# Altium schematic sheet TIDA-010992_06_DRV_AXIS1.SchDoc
size 431 x 279 mm; Date: Not shown in title block; ApprovedBy: Not shown in title block; CheckedBy: Not shown in title block; Author: Not shown in title block; CompanyName: Not shown in title block; Engineer: Not shown in title block; Organization: Not shown in title block; Address1: Not shown in title block; Address2: Not shown in title block; Address3: Not shown in title block; Address4: Not shown in title block; DocumentNumber: 6; Revision: Use project parameter SCH_Rev; SheetNumber: 6; SheetTotal: 13; PageSetup: Record=PageOptions¦CenterHorizontal=True¦CenterVertical=True¦PrintScale=1.00¦XCorrection=1.00¦YCorrection=1.00¦PrintKind=0¦BorderSize=5000000¦LeftOffset=0¦BottomOffset=0¦Orientation=2¦PaperLength=1000¦PaperWidth=1000¦Scale=100¦PaperSource=15¦PrintQuality=600¦MediaType=1¦DitherType=10¦PaperKind=Letter¦PrintScaleMode=1
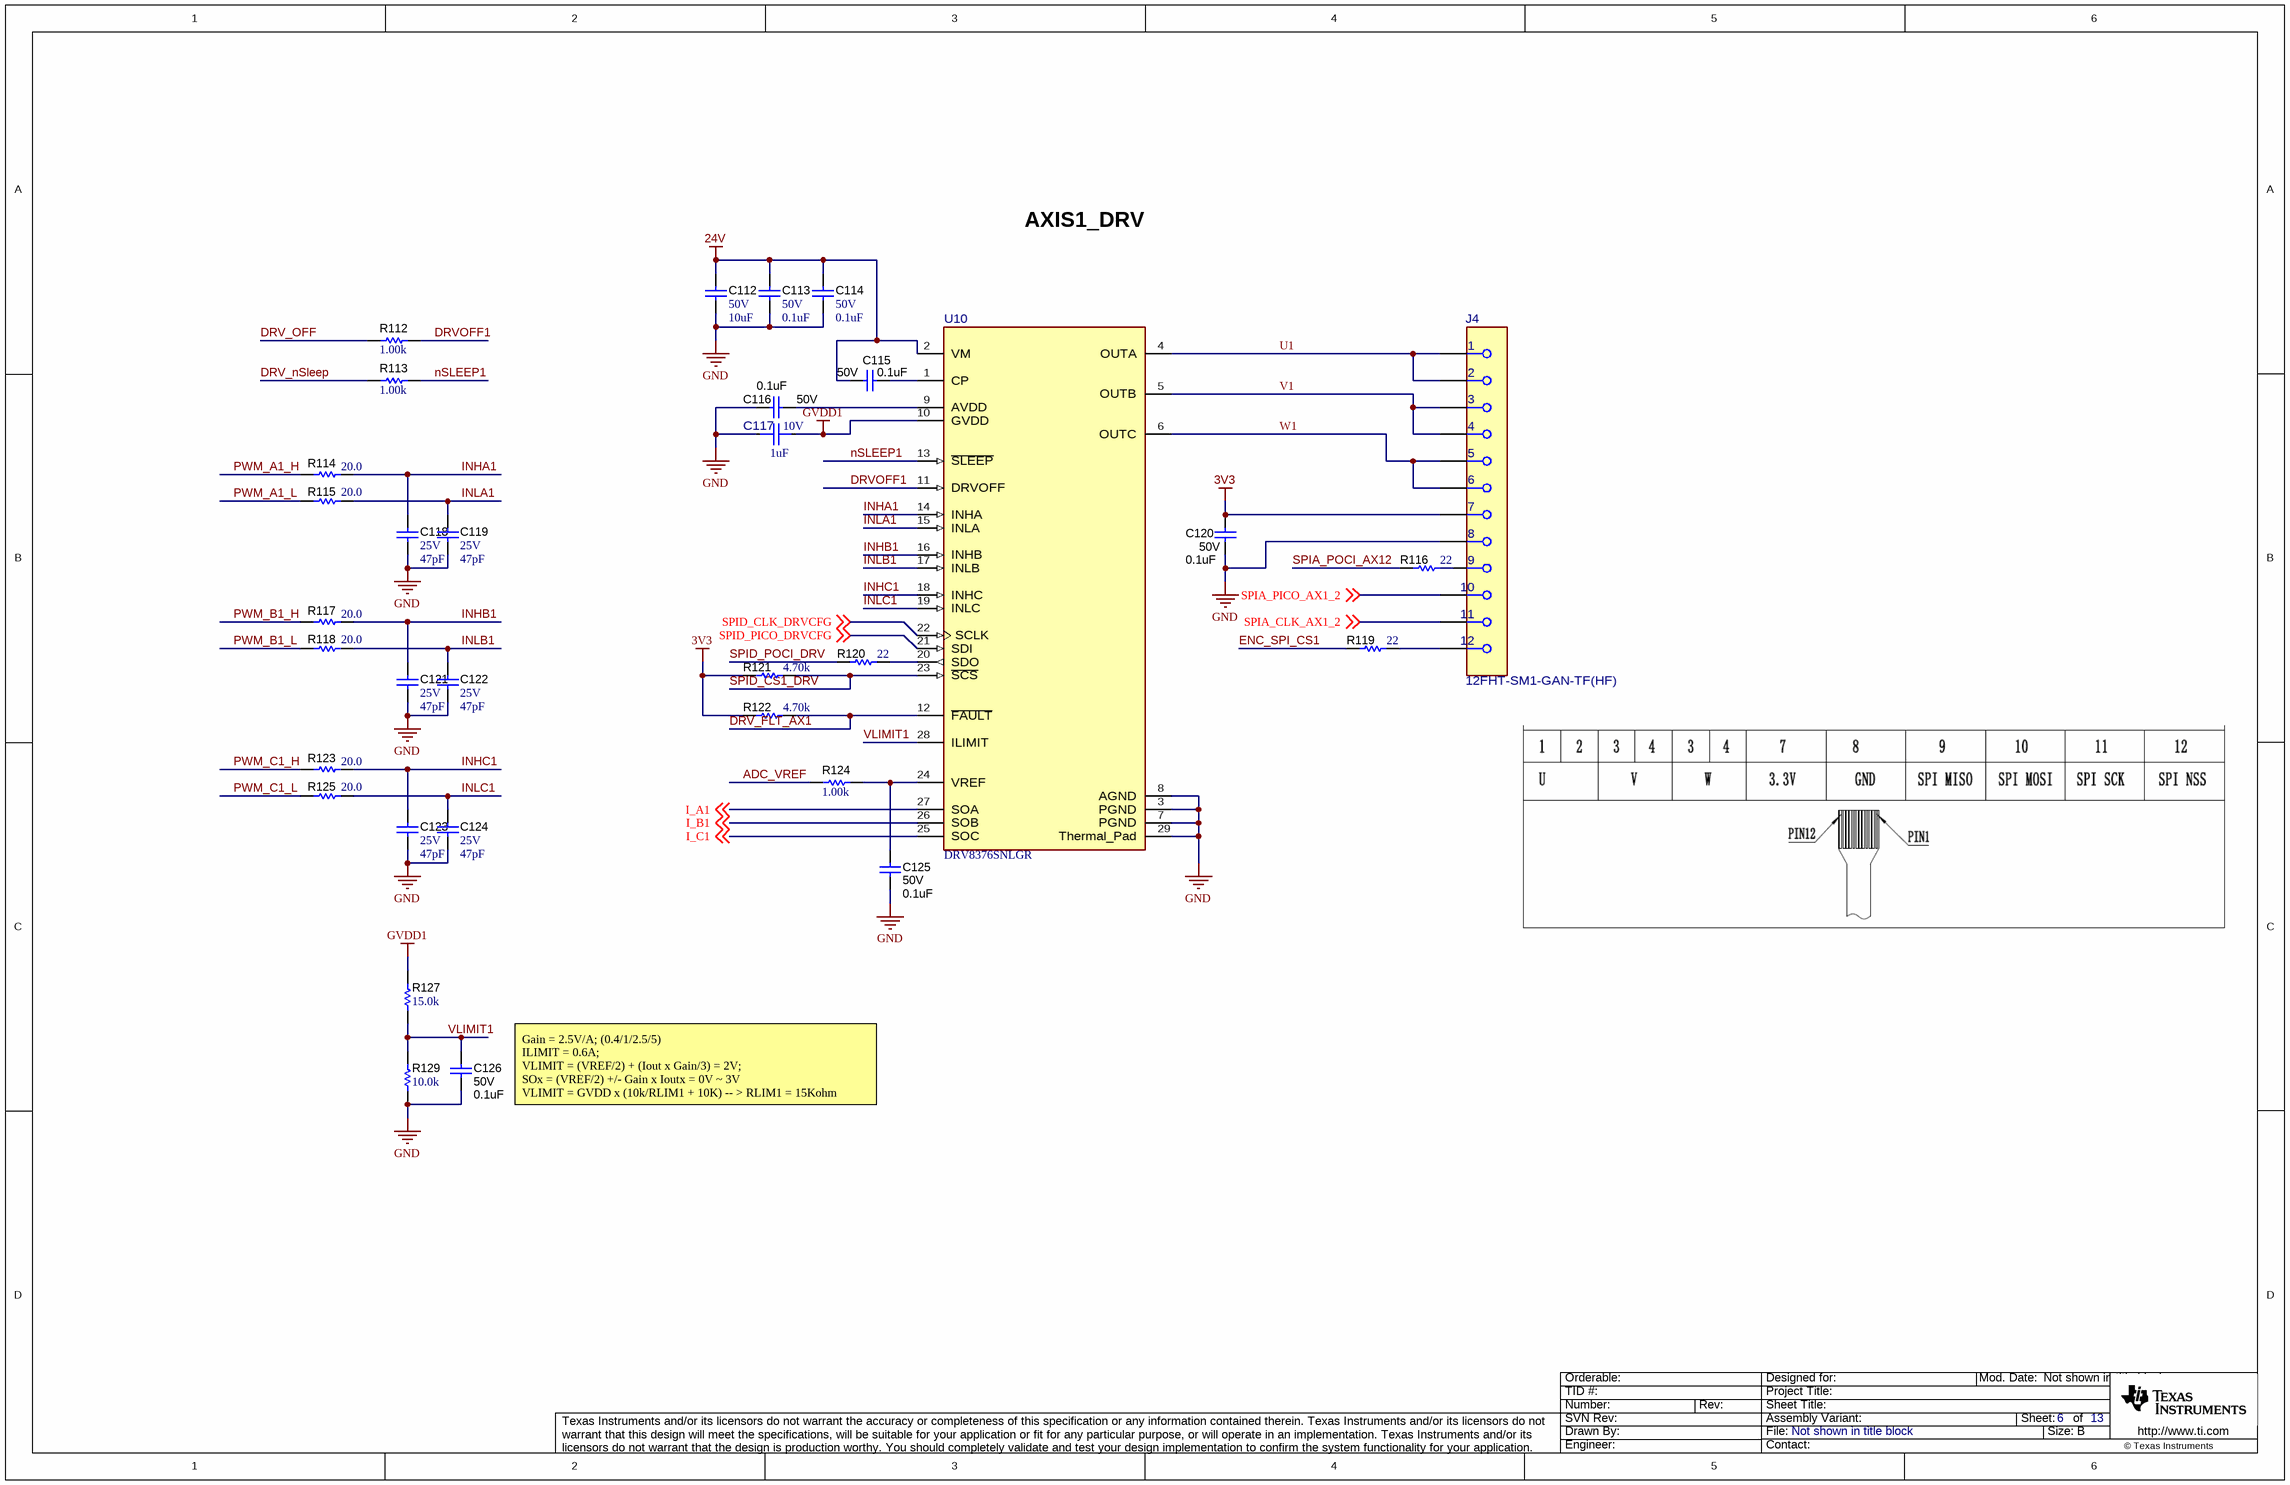
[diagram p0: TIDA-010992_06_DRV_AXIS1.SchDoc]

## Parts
C112  VDC_V: 50V  ValueDisplayed: 10uF  [1206_180]  (hidden comment: CL31B106KBHNNNE)
C113  VDC_V: 50V  ValueDisplayed: 0.1uF  [0402]  (hidden comment: C1005X7R1H104K050BE)
C114  VDC_V: 50V  ValueDisplayed: 0.1uF  [0402]  (hidden comment: C1005X7R1H104K050BE)
C115  VDC_V: 50V  ValueDisplayed: 0.1uF  [0402]  (hidden comment: CGA2B3X7R1H104M050BB)
C116  VDC_V: 50V  ValueDisplayed: 0.1uF  [0402]  (hidden comment: CGA2B3X7R1H104M050BB)
C117  VDC_V: 10V  ValueDisplayed: 1uF  [FP-GMC04X7R105K10NT_0402-MFG]  (hidden comment: GMC04X7R105K10NT)
C118  VDC_V: 25V  ValueDisplayed: 47pF  [0201_033]  (hidden comment: GRM0335C1E470JA01D)
C119  VDC_V: 25V  ValueDisplayed: 47pF  [0201_033]  (hidden comment: GRM0335C1E470JA01D)
C120  VDC_V: 50V  ValueDisplayed: 0.1uF  [0402]  (hidden comment: CGA2B3X7R1H104M050BB)
C121  VDC_V: 25V  ValueDisplayed: 47pF  [0201_033]  (hidden comment: GRM0335C1E470JA01D)
C122  VDC_V: 25V  ValueDisplayed: 47pF  [0201_033]  (hidden comment: GRM0335C1E470JA01D)
C123  VDC_V: 25V  ValueDisplayed: 47pF  [0201_033]  (hidden comment: GRM0335C1E470JA01D)
C124  VDC_V: 25V  ValueDisplayed: 47pF  [0201_033]  (hidden comment: GRM0335C1E470JA01D)
C125  VDC_V: 50V  ValueDisplayed: 0.1uF  [0402]  (hidden comment: CGA2B3X7R1H104M050BB)
C126  VDC_V: 50V  ValueDisplayed: 0.1uF  [0402]  (hidden comment: CGA2B3X7R1H104M050BB)
J4  12FHT-SM1-GAN-TF(HF)  [FP-12FHT-SM1-GAN-TF(HF)_CONN_FPC_12-MFG]
R112  ValueDisplayed: 1.00k  [0402]  (hidden comment: CRCW04021K00FKED)
R113  ValueDisplayed: 1.00k  [0402]  (hidden comment: CRCW04021K00FKED)
R114  ValueDisplayed: 20.0  [0201_033]  (hidden comment: CRCW020120R0FNED)
R115  ValueDisplayed: 20.0  [0201_033]  (hidden comment: CRCW020120R0FNED)
R116  ValueDisplayed: 22  [0201]  (hidden comment: ERJ-1GNJ220C)
R117  ValueDisplayed: 20.0  [0201_033]  (hidden comment: CRCW020120R0FNED)
R118  ValueDisplayed: 20.0  [0201_033]  (hidden comment: CRCW020120R0FNED)
R119  ValueDisplayed: 22  [0201]  (hidden comment: ERJ-1GNJ220C)
R120  ValueDisplayed: 22  [0201]  (hidden comment: ERJ-1GNJ220C)
R121  ValueDisplayed: 4.70k  [0201]  (hidden comment: RC0201FR-7D4K7L)
R122  ValueDisplayed: 4.70k  [0201]  (hidden comment: RC0201FR-7D4K7L)
R123  ValueDisplayed: 20.0  [0201_033]  (hidden comment: CRCW020120R0FNED)
R124  ValueDisplayed: 1.00k  [0402]  (hidden comment: CRCW04021K00FKED)
R125  ValueDisplayed: 20.0  [0201_033]  (hidden comment: CRCW020120R0FNED)
R127  ValueDisplayed: 15.0k  [0402]  (hidden comment: RC0402FR-0715KL)
R129  ValueDisplayed: 10.0k  [0402L]  (hidden comment: CRCW040210K0FKED)
U10  DRV8376SNLGR  [NLG0028A-MFG]

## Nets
3V3: C120.2 J4.7 R121.2 R122.2
24V: C112.1 C113.1 C114.1 C115.1 U10.2(VM)
GND: C112.2 C113.2 C114.2 C116.1 C117.1 C118.2 C119.2 C120.1 C121.2 C122.2 C123.2 C124.2 C125.1 C126.1 J4.8 R129.1 U10.3(PGND) U10.7(PGND) U10.8(AGND) U10.29(Thermal_Pad)
GVDD1: C117.2 R127.2 U10.10(GVDD)
ADC_VREF: R124.1
DRV_FLT_AX1: R122.1 U10.12(~{FAULT})
DRV_nSleep: R113.1
DRV_OFF: R112.1
DRVOFF1: R112.2 U10.11(DRVOFF)
ENC_SPI_CS1: R119.1
I_A1: U10.27(SOA) ; off-sheet I_A1
I_B1: U10.26(SOB) ; off-sheet I_B1
I_C1: U10.25(SOC) ; off-sheet I_C1
INHA1: C118.1 R114.2 U10.14(INHA)
INHB1: C121.1 R117.2 U10.16(INHB)
INHC1: C123.1 R123.2 U10.18(INHC)
INLA1: C119.1 R115.2 U10.15(INLA)
INLB1: C122.1 R118.2 U10.17(INLB)
INLC1: C124.1 R125.2 U10.19(INLC)
nSLEEP1: R113.2 U10.13(~{SLEEP})
PWM_A1_H: R114.1
PWM_A1_L: R115.1
PWM_B1_H: R117.1
PWM_B1_L: R118.1
PWM_C1_H: R123.1
PWM_C1_L: R125.1
SPIA_CLK_AX1_2: J4.11 ; off-sheet SPIA_CLK_AX1_2
SPIA_PICO_AX1_2: J4.10 ; off-sheet SPIA_PICO_AX1_2
SPIA_POCI_AX12: R116.1
SPID_CLK_DRVCFG: U10.22(SCLK) ; off-sheet SPID_CLK_DRVCFG
SPID_CS1_DRV: R121.1 U10.23(~{SCS})
SPID_PICO_DRVCFG: U10.21(SDI) ; off-sheet SPID_PICO_DRVCFG
SPID_POCI_DRV: R120.1
U1: J4.1 J4.2 U10.4(OUTA)
V1: J4.3 J4.4 U10.5(OUTB)
VLIMIT1: C126.2 R127.1 R129.2 U10.28(ILIMIT)
W1: J4.5 J4.6 U10.6(OUTC)
NetC115_2: C115.2 U10.1(CP)
NetC116_2: C116.2 U10.9(AVDD)
NetC125_2: C125.2 R124.2 U10.24(VREF)
NetJ4_9: J4.9 R116.2
NetJ4_12: J4.12 R119.2
NetR120_2: R120.2 U10.20(SDO)

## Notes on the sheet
- AXIS1_DRV
- Gain = 2.5V/A; (0.4/1/2.5/5)
  ILIMIT = 0.6A;
  VLIMIT = (VREF/2) + (Iout x Gain/3) = 2V;
  SOx = (VREF/2) +/- Gain x Ioutx = 0V ~ 3V
  VLIMIT = GVDD x (10k/RLIM1 + 10K) -- > RLIM1 = 15Kohm

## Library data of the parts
C112 = CMP-0008802-2: CAP, CERM, 10 uF, 50 V, +/- 10%, X7R, 1206; Manufacturer: Samsung; TaMin_C: -55°C; Polarized: N; SizeAreaWB_mm2: 10.92; Value1: Unknown; U/M: EA; Value: 10uF; TaMax_C: 125°C; SizeZ_mm: 1.8; SizeX_mm: 3.2; SizeY_mm: 1.6; Cap_Case: 1206; SizeArea_mm2: 5.12; Cap_F: 10µF; AEC Category: Q200
C113 C114 = CMP-0064946-2: CAP, CERM, 0.1 uF, 50 V,+/- 10%, X7R, 0402; Manufacturer: TDK; TaMin_C: -55°C; Polarized: N; SizeAreaWB_mm2: 3; Value1: Unknown; U/M: EA; Value: 0.1uF; TaMax_C: 125°C; SizeZ_mm: 0.6; SizeX_mm: 1; SizeY_mm: 0.5; Cap_F: 100nF; AEC Category: Q200
C115 C116 C120 C125 C126 = CMP-0006326-2: CAP, CERM, 0.1 uF, 50 V, +/- 20%, X7R, AEC-Q200 Grade 1, 0402; Manufacturer: TDK; TaMin_C: -55°C; Polarized: N; SizeAreaWB_mm2: 3; Value1: Unknown; U/M: EA; Value: 0.1uF; TaMax_C: 125°C; SizeZ_mm: 0.6; SizeX_mm: 1; SizeY_mm: 0.5; AEC Qualified: Y; Cap_F: 100nF; AEC Category: Q200
C117 = CMP-0093200-1: 1µF ±10% 10V Ceramic Capacitor X7R 0402 (1005 Metric); Manufacturer: Cal-Chip Electronics; TempCo: 15%; SizeZ_mm: 0.6mm; AEC Qualified: No
C118 C119 C121-C124 = CMP-0009662-3: CAP, CERM, 47 pF, 25 V, +/- 5%, C0G/NP0, 0201; Manufacturer: MuRata; TaMin_C: -55°C; Polarized: N; SizeAreaWB_mm2: 2.08; Value1: Unknown; U/M: EA; Value: 47pF; TaMax_C: 125°C; SizeZ_mm: 0.33; SizeX_mm: 0.6; SizeY_mm: 0.3; Cap_Case: 0201; SizeArea_mm2: 0.18; AEC Category: Q200
J4 = CMP-0126588-1: Conn FPC Connector F 12 POS 0.5mm Solder Ver SMD T/R; Manufacturer: JST; ContactFinish: Gold,Nickel; Current_A: 500mA; Voltage_V: 50V; AEC Qualified: No; Conn Gender: Female; Conn Orientation: Vertical; Is Female: yes; SizeZ_mm: 3.3mm; Standoff Height: 0.13mm
R112 R113 R124 = CMP-0026071-3: RES, 1.00 k, 1%, 0.063 W, AEC-Q200 Grade 0, 0402; Manufacturer: Vishay-Dale; Power_W: 63mW; TempCo: 100 ppm/C; Value_Code: 1k00; Value: 1.00k; EIA_Code: E96; Res_ohm: 1k; SizeX_mm: 1; SizeY_mm: 0.5; SizeZ_mm: 0.6; Value2: 0.063W; AEC Qualified: Y; VDC_V: 50V; AEC Category: Q200; AEC Grade: 0
R114 R115 R117 R118 R123 R125 = CMP-0078192-1: RES, 20.0, 1%, 0.05 W, 0201; Manufacturer: Vishay-Dale; Value_Code: 20R0; SizeArea_mm2: 0.18; AEC Qualified: N; AEC Category: Q200; Res_ohm: 20; Value: 20.0; SizeZ_mm: 0.33; EIA_Code: E96; TempCo: 200 ppm/C; Power_W: 50mW; VDC_V: 30V; SizeY_mm: 0.3; Value2: 0.05W; U/M: EA; SizeX_mm: 0.6
R116 R119 R120 = CMP-0027015-3: RES, 22, 5%, 0.05 W, AEC-Q200 Grade 1, 0201; Manufacturer: Panasonic; Power_W: 50mW; TempCo: 200 ppm/C; Value_Code: 22R0; U/M: EA; Value: 22; EIA_Code: E24; SizeX_mm: 0.6; SizeY_mm: 0.3; SizeZ_mm: 0.26; Value2: 0.05W; SizeArea_mm2: 0.18; AEC Qualified: Y; AEC Grade: 1; AEC Category: Q200
R121 R122 = CMP-0028031-1: RES, 4.70 k, 1%, 0.05 W, 0201; Manufacturer: Yageo America; Power_W: 50mW; TempCo: 200 ppm/C; Value_Code: 4k70; U/M: EA; Value: 4.70k; Res_ohm: 4.7k; SizeX_mm: 0.6; SizeY_mm: 0.3; SizeZ_mm: 0.26; Value2: 0.05W; SizeArea_mm2: 0.18; AEC Qualified: N; VDC_V: 25V; AEC Category: Q200
R127 = CMP-0078583-1: RES, 15.0 k, 1%, 0.063 W, 0402; Manufacturer: Yageo America; Power_W: 63mW; Green_Lifecycle: Active; TempCo: 100 ppm/C; Value_Code: 15k0; Green_REACh: Passed; Value: 15.0k; EIA_Code: E96; Res_ohm: 15k; SizeX_mm: 1; SizeY_mm: 0.5; SizeZ_mm: 0.6; Value2: 0.063W; AEC Qualified: N; AEC Category: Q200
R129 = CMP-0025958-3: RES, 10.0 k, 1%, 0.063 W, AEC-Q200 Grade 0, 0402; Manufacturer: Vishay-Dale; Power_W: 63mW; TempCo: 100 ppm/C; Value_Code: 10k0; Value: 10.0k; EIA_Code: E96; Res_ohm: 10k; SizeX_mm: 1; SizeY_mm: 0.5; SizeZ_mm: 0.6; Value2: 0.063W; AEC Qualified: Y; VDC_V: 50V; AEC Category: Q200; AEC Grade: 0
U10 = CMP-0122073-1: Three-Phase Integrated FET Motor Driver; Manufacturer: Texas Instruments; SizeZ_mm: 1mm; AEC Qualified: No; Max Supply Voltage: 65V; Min Supply Voltage: 4.5V; Motor Type: Brushless DC; Nominal Supply Current: 6.6-8.2mA; Number Of Outputs: 3; Standoff Height: 0mm; Switching Frequency: 100kHz; TaMax_C: +125°C; TaMin_C: -40°C; TJmax_C: +150°C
